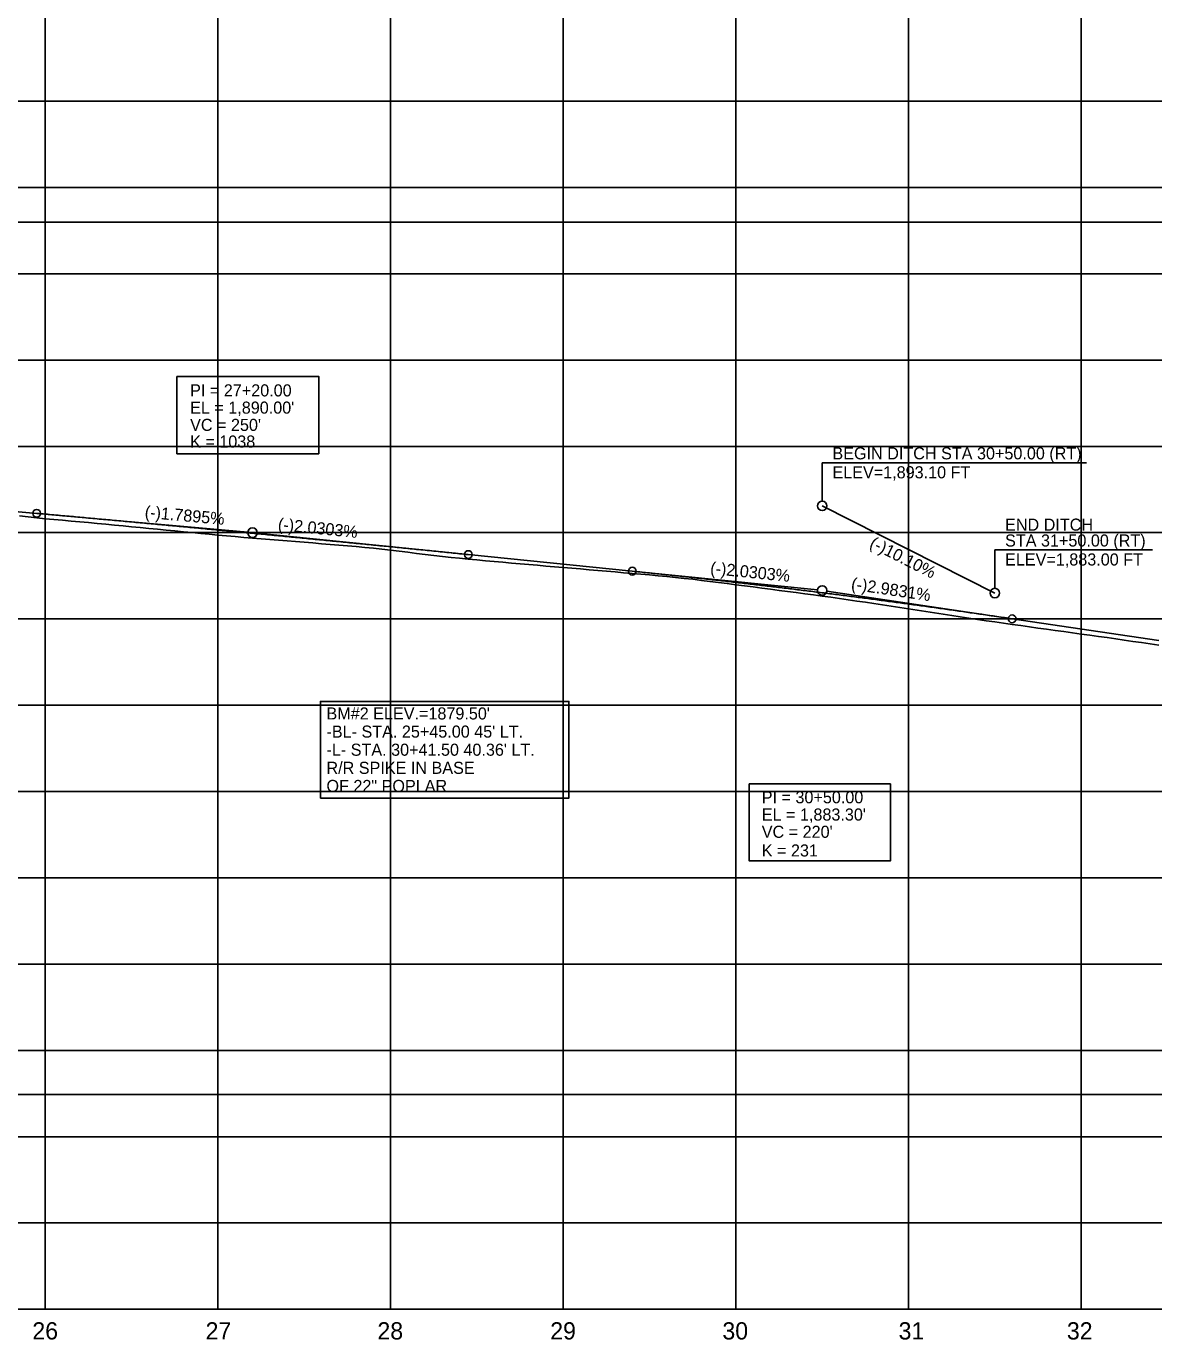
# Model space of a CAD drawing. Extents: x 553912 to 567693, y 512355 to 537539.
# Drawn here: x 558838 to 559491, y 513588 to 514349 of the extents above; entities that cross this region are included whole.
import ezdxf

# ---------------------------------------------------------------- set-up
doc = ezdxf.new("R2010")
doc.units = 0
for name, color, linetype in [('Exist DTM Spot Elevation Text', 7, 'Continuous'), ('Exist Profile Cell', 7, 'Continuous'), ('Exist Vertical Profile Ground Line', 7, 'Continuous'), ('Exist Vertical Profile Horizontal Axis Label Major', 7, 'Continuous'), ('Prop Vertical Profile Curve Label', 7, 'Continuous'), ('Prop Vertical Profile Ditch Grade Right', 7, 'Continuous'), ('Prop Vertical Profile Ditch Grade Right Label', 7, 'Continuous'), ('Prop Vertical Profile Grade', 7, 'Continuous'), ('Prop Vertical Profile Grade Label', 7, 'Continuous'), ('Prop VPI Label', 7, 'Continuous'), ('Scratch_Level_5', 7, 'Continuous'), ('Sheet Profile Grid Major CELL', 7, 'Continuous')]:
    doc.layers.add(name, color=color, linetype=linetype)

msp = doc.modelspace()

# ---------------------------------------------------------------- linework, layer by layer
at = {"layer": 'Exist DTM Spot Elevation Text'}
msp.add_lwpolyline([(559008.8, 513901.64), (559152.74, 513901.64), (559152.74, 513957.64), (559008.8, 513957.64)], close=True, dxfattribs=at)
at = {"layer": 'Exist Profile Cell'}
msp.add_line((557249.45, 513605.4), (563849.45, 513605.4), dxfattribs=at)
msp.add_line((557249.45, 513605.4), (563849.45, 513605.4), dxfattribs=at)
at = {"layer": 'Exist Vertical Profile Ground Line'}
for points in [[(558834.45, 514065.1), (558839.45, 514064.48), (558844.45, 514063.94), (558849.45, 514063.49), (558854.45, 514063.04), (558859.45, 514062.59), (558864.45, 514062.14), (558869.45, 514061.69), (558874.45, 514061.24), (558879.45, 514060.79), (558884.45, 514060.32), (558889.45, 514059.83), (558894.45, 514059.35), (558899.45, 514058.86), (558904.45, 514058.37), (558909.45, 514057.89), (558914.45, 514057.41), (558919.45, 514056.93), (558924.45, 514056.45), (558929.45, 514055.97), (558934.45, 514055.48), (558939.45, 514055), (558944.45, 514054.52), (558949.45, 514054.04), (558954.45, 514053.57), (558959.45, 514053.09), (558964.45, 514052.69), (558969.45, 514052.29), (558974.45, 514051.88), (558979.45, 514051.47), (558984.45, 514051.06), (558989.45, 514050.65), (558994.45, 514050.24), (558999.45, 514049.83), (559004.45, 514049.43), (559009.45, 514049), (559014.45, 514048.58), (559019.45, 514048.15), (559024.45, 514047.73), (559029.45, 514047.3), (559034.45, 514046.83), (559039.45, 514046.4), (559044.45, 514045.87), (559049.45, 514045.25), (559054.45, 514044.64), (559059.45, 514044.02), (559064.45, 514043.4), (559069.45, 514042.79), (559074.45, 514042.19), (559079.45, 514041.57), (559084.45, 514041.05), (559089.45, 514040.58), (559094.45, 514040.1), (559099.45, 514039.63), (559104.45, 514039.15), (559109.45, 514038.68), (559114.45, 514038.22), (559119.45, 514037.74), (559124.45, 514037.32), (559129.45, 514036.91), (559134.45, 514036.49), (559139.45, 514036.08), (559144.45, 514035.66), (559149.45, 514035.23), (559154.45, 514034.79), (559159.45, 514034.36), (559164.45, 514033.93), (559169.45, 514033.5), (559174.45, 514033.08), (559179.45, 514032.64), (559184.45, 514032.21), (559189.45, 514031.78), (559194.45, 514031.34), (559199.45, 514030.9), (559204.45, 514030.46), (559209.45, 514029.98), (559214.45, 514029.46), (559219.45, 514028.93), (559224.45, 514028.38), (559229.45, 514027.77), (559234.45, 514027.14), (559239.45, 514026.51), (559244.45, 514025.87), (559249.45, 514025.22)], [(558834.45, 514065.1), (558839.45, 514064.48), (558844.45, 514063.94), (558849.45, 514063.49), (558854.45, 514063.04), (558859.45, 514062.59), (558864.45, 514062.14), (558869.45, 514061.69), (558874.45, 514061.24), (558879.45, 514060.79), (558884.45, 514060.32), (558889.45, 514059.83), (558894.45, 514059.35), (558899.45, 514058.86), (558904.45, 514058.37), (558909.45, 514057.89), (558914.45, 514057.41), (558919.45, 514056.93), (558924.45, 514056.45), (558929.45, 514055.97), (558934.45, 514055.48), (558939.45, 514055), (558944.45, 514054.52), (558949.45, 514054.04), (558954.45, 514053.57), (558959.45, 514053.09), (558964.45, 514052.69), (558969.45, 514052.29), (558974.45, 514051.88), (558979.45, 514051.47), (558984.45, 514051.06), (558989.45, 514050.65), (558994.45, 514050.24), (558999.45, 514049.83), (559004.45, 514049.43), (559009.45, 514049), (559014.45, 514048.58), (559019.45, 514048.15), (559024.45, 514047.73), (559029.45, 514047.3), (559034.45, 514046.83), (559039.45, 514046.4), (559044.45, 514045.87), (559049.45, 514045.25), (559054.45, 514044.64), (559059.45, 514044.02), (559064.45, 514043.4), (559069.45, 514042.79), (559074.45, 514042.19), (559079.45, 514041.57), (559084.45, 514041.05), (559089.45, 514040.58), (559094.45, 514040.1), (559099.45, 514039.63), (559104.45, 514039.15), (559109.45, 514038.68), (559114.45, 514038.22), (559119.45, 514037.74), (559124.45, 514037.32), (559129.45, 514036.91), (559134.45, 514036.49), (559139.45, 514036.08), (559144.45, 514035.66), (559149.45, 514035.23), (559154.45, 514034.79), (559159.45, 514034.36), (559164.45, 514033.93), (559169.45, 514033.5), (559174.45, 514033.08), (559179.45, 514032.64), (559184.45, 514032.21), (559189.45, 514031.78), (559194.45, 514031.34), (559199.45, 514030.9), (559204.45, 514030.46), (559209.45, 514029.98), (559214.45, 514029.46), (559219.45, 514028.93), (559224.45, 514028.38), (559229.45, 514027.77), (559234.45, 514027.14), (559239.45, 514026.51), (559244.45, 514025.87), (559249.45, 514025.22)], [(559249.45, 514025.22), (559254.45, 514024.57), (559259.45, 514023.92), (559264.45, 514023.27), (559269.45, 514022.62), (559274.45, 514021.97), (559279.45, 514021.32), (559284.45, 514020.66), (559289.45, 514019.99), (559294.45, 514019.33), (559299.45, 514018.64), (559304.45, 514017.93), (559309.45, 514017.23), (559314.45, 514016.52), (559319.45, 514015.77), (559324.45, 514015.03), (559329.45, 514014.28), (559334.45, 514013.53), (559339.45, 514012.76), (559344.45, 514011.98), (559349.45, 514011.21), (559354.45, 514010.45), (559359.45, 514009.67), (559364.45, 514008.9), (559369.45, 514008.13), (559374.45, 514007.37), (559379.45, 514006.62), (559384.45, 514005.87), (559389.45, 514005.12), (559394.45, 514004.39), (559399.45, 514003.67), (559404.45, 514002.94), (559409.45, 514002.23), (559414.45, 514001.52), (559419.45, 514000.81), (559424.45, 514000.1), (559429.45, 513999.39), (559434.45, 513998.69), (559439.45, 513998.06), (559444.45, 513997.36), (559449.45, 513996.66), (559454.45, 513996), (559459.45, 513995.32), (559464.45, 513994.62), (559469.45, 513993.92), (559474.45, 513993.11), (559479.45, 513992.39), (559484.45, 513991.68), (559489.45, 513990.95), (559494.45, 513990.2)], [(559249.45, 514025.22), (559254.45, 514024.57), (559259.45, 514023.92), (559264.45, 514023.27), (559269.45, 514022.62), (559274.45, 514021.97), (559279.45, 514021.32), (559284.45, 514020.66), (559289.45, 514019.99), (559294.45, 514019.33), (559299.45, 514018.64), (559304.45, 514017.93), (559309.45, 514017.23), (559314.45, 514016.52), (559319.45, 514015.77), (559324.45, 514015.03), (559329.45, 514014.28), (559334.45, 514013.53), (559339.45, 514012.76), (559344.45, 514011.98), (559349.45, 514011.21), (559354.45, 514010.45), (559359.45, 514009.67), (559364.45, 514008.9), (559369.45, 514008.13), (559374.45, 514007.37), (559379.45, 514006.62), (559384.45, 514005.87), (559389.45, 514005.12), (559394.45, 514004.39), (559399.45, 514003.67), (559404.45, 514002.94), (559409.45, 514002.23), (559414.45, 514001.52), (559419.45, 514000.81), (559424.45, 514000.1), (559429.45, 513999.39), (559434.45, 513998.69), (559439.45, 513998.06), (559444.45, 513997.36), (559449.45, 513996.66), (559454.45, 513996), (559459.45, 513995.32), (559464.45, 513994.62), (559469.45, 513993.92), (559474.45, 513993.11), (559479.45, 513992.39), (559484.45, 513991.68), (559489.45, 513990.95), (559494.45, 513990.2)]]:
    msp.add_lwpolyline(points, dxfattribs=at)
at = {"layer": 'Prop Vertical Profile Curve Label'}
for centre in [(558844.45, 514066.58), (559094.45, 514042.71), (559189.45, 514033.07), (559409.45, 514005.49)]:
    msp.add_circle(centre, 2.25, dxfattribs=at)
at = {"layer": 'Prop Vertical Profile Ditch Grade Right'}
msp.add_line((559299.45, 514070.9), (559399.45, 514020.4), dxfattribs=at)
at = {"layer": 'Prop Vertical Profile Ditch Grade Right Label'}
for p, q in [((559299.45, 514073.65), (559299.45, 514095.87)), ((559452.63, 514095.87), (559299.45, 514095.87)), ((559399.45, 514023.15), (559399.45, 514045.37)), ((559490.78, 514045.37), (559399.45, 514045.37))]:
    msp.add_line(p, q, dxfattribs=at)
for centre in [(559299.45, 514070.9), (559399.45, 514020.4)]:
    msp.add_circle(centre, 2.75, dxfattribs=at)
at = {"layer": 'Prop Vertical Profile Grade'}
for p, q in [((558506.95, 514096.78), (558844.45, 514066.58)), ((559094.45, 514042.71), (559189.45, 514033.07)), ((559409.45, 514005.49), (559494.45, 513992.82))]:
    msp.add_line(p, q, dxfattribs=at)
for points in [[(558844.45, 514066.58), (558849.45, 514066.14), (558854.45, 514065.69), (558859.45, 514065.24), (558864.45, 514064.79), (558869.45, 514064.33), (558874.45, 514063.88), (558879.45, 514063.42), (558884.45, 514062.97), (558889.45, 514062.51), (558894.45, 514062.05), (558899.45, 514061.59), (558904.45, 514061.13), (558909.45, 514060.67), (558914.45, 514060.2), (558919.45, 514059.74), (558924.45, 514059.27), (558929.45, 514058.81), (558934.45, 514058.34), (558939.45, 514057.87), (558944.45, 514057.4), (558949.45, 514056.92), (558954.45, 514056.45), (558959.45, 514055.98), (558964.45, 514055.5), (558969.45, 514055.02), (558974.45, 514054.55), (558979.45, 514054.07), (558984.45, 514053.59), (558989.45, 514053.1), (558994.45, 514052.62), (558999.45, 514052.14), (559004.45, 514051.65), (559009.45, 514051.17), (559014.45, 514050.68), (559019.45, 514050.19), (559024.45, 514049.7), (559029.45, 514049.21), (559034.45, 514048.72), (559039.45, 514048.22), (559044.45, 514047.73), (559049.45, 514047.23), (559054.45, 514046.73), (559059.45, 514046.23), (559064.45, 514045.73), (559069.45, 514045.23), (559074.45, 514044.73), (559079.45, 514044.23), (559084.45, 514043.72), (559089.45, 514043.22), (559094.45, 514042.71)], [(559189.45, 514033.07), (559193.85, 514032.62), (559198.25, 514032.17), (559202.65, 514031.71), (559207.05, 514031.25), (559211.45, 514030.78), (559215.85, 514030.31), (559220.25, 514029.84), (559224.65, 514029.36), (559229.05, 514028.88), (559233.45, 514028.39), (559237.85, 514027.9), (559242.25, 514027.41), (559246.65, 514026.91), (559251.05, 514026.4), (559255.45, 514025.9), (559259.85, 514025.38), (559264.25, 514024.87), (559268.65, 514024.35), (559273.05, 514023.82), (559277.45, 514023.3), (559281.85, 514022.76), (559286.25, 514022.23), (559290.65, 514021.68), (559295.05, 514021.14), (559299.45, 514020.59), (559303.85, 514020.04), (559308.25, 514019.48), (559312.65, 514018.92), (559317.05, 514018.35), (559321.45, 514017.78), (559325.85, 514017.21), (559330.25, 514016.63), (559334.65, 514016.04), (559339.05, 514015.46), (559343.45, 514014.87), (559347.85, 514014.27), (559352.25, 514013.67), (559356.65, 514013.07), (559361.05, 514012.46), (559365.45, 514011.85), (559369.85, 514011.23), (559374.25, 514010.61), (559378.65, 514009.98), (559383.05, 514009.36), (559387.45, 514008.72), (559391.85, 514008.09), (559396.25, 514007.44), (559400.65, 514006.8), (559405.05, 514006.15), (559409.45, 514005.49)]]:
    msp.add_spline(points, degree=3, dxfattribs=at)
at = {"layer": 'Prop VPI Label'}
for p, q in [((558844.45, 514066.58), (558966.71, 514055.65)), ((559094.45, 514042.71), (558972.19, 514055.12)), ((559189.45, 514033.07), (559296.72, 514022.18)), ((559409.45, 514005.49), (559302.17, 514021.49))]:
    msp.add_line(p, q, dxfattribs=at)
for points in [[(558925.69, 514145.97), (559007.81, 514145.97), (559007.81, 514101.15), (558925.69, 514101.15)], [(559257.22, 513909.83), (559338.96, 513909.83), (559338.96, 513865.22), (559257.22, 513865.22)]]:
    msp.add_lwpolyline(points, close=True, dxfattribs=at)
for centre in [(558969.45, 514055.4), (559299.45, 514021.9)]:
    msp.add_circle(centre, 2.75, dxfattribs=at)
at = {"layer": 'Scratch_Level_5'}
msp.add_lwpolyline([(558649.45, 514235.4), (558643.76, 513729.91), (560043.76, 513729.91), (560049.45, 514074.35), (559899.4, 514074.35), (559899.4, 514235.4)], close=True, dxfattribs=at)
at = {"layer": 'Sheet Profile Grid Major CELL'}
for p, q in [((558849.45, 513605.4), (558849.45, 514805.4)), ((558949.45, 513605.4), (558949.45, 514805.4)), ((559049.45, 513605.4), (559049.45, 514805.4)), ((559149.45, 513605.4), (559149.45, 514805.4)), ((559249.45, 513605.4), (559249.45, 514805.4)), ((559349.45, 513605.4), (559349.45, 514805.4)), ((559449.45, 513605.4), (559449.45, 514805.4)), ((563849.45, 514305.4), (557249.45, 514305.4)), ((563849.45, 514255.4), (557249.45, 514255.4)), ((563849.45, 514205.4), (557249.45, 514205.4)), ((563849.45, 514155.4), (557249.45, 514155.4)), ((563849.45, 514105.4), (557249.45, 514105.4)), ((563849.45, 514055.4), (557249.45, 514055.4)), ((563849.45, 514005.4), (557249.45, 514005.4)), ((563849.45, 513955.4), (557249.45, 513955.4)), ((563849.45, 513905.4), (557249.45, 513905.4)), ((563849.45, 513855.4), (557249.45, 513855.4)), ((563849.45, 513805.4), (557249.45, 513805.4)), ((563849.45, 513755.4), (557249.45, 513755.4)), ((563849.45, 513705.4), (557249.45, 513705.4)), ((563849.45, 513655.4), (557249.45, 513655.4))]:
    msp.add_line(p, q, dxfattribs=at)

# ---------------------------------------------------------------- texts
at = {"layer": 'Exist DTM Spot Elevation Text'}
for s, p in [("BM#2 ELEV.=1879.50'", (559012.3, 513947.14)), ("-BL- STA. 25+45.00 45' LT.", (559012.3, 513936.64)), ("-L- STA. 30+41.50 40.36' LT.", (559012.3, 513926.14)), ('R/R SPIKE IN BASE', (559012.3, 513915.64)), ('OF 22" POPLAR', (559012.3, 513905.14))]:
    msp.add_text(s, height=7, dxfattribs=at).set_placement(p)
at = {"layer": 'Exist Vertical Profile Horizontal Axis Label Major'}
for s, p in [('26', (558841.94, 513587.9)), ('26', (558841.94, 513587.9)), ('27', (558942.3, 513587.9)), ('27', (558942.3, 513587.9)), ('28', (559041.83, 513587.9)), ('28', (559041.83, 513587.9)), ('29', (559141.92, 513587.9)), ('29', (559141.92, 513587.9)), ('30', (559241.64, 513587.9)), ('30', (559241.64, 513587.9)), ('31', (559343.71, 513587.9)), ('31', (559343.71, 513587.9)), ('32', (559441.21, 513587.9)), ('32', (559441.21, 513587.9))]:
    msp.add_text(s, height=10, dxfattribs=at).set_placement(p)
at = {"layer": 'Prop Vertical Profile Curve Label'}
for s, p in [("VC = 250'", (558933.32, 514114.35)), ('K = 1038', (558933.32, 514104.7)), ("VC = 220'", (559264.45, 513878.58)), ('K = 231', (559264.45, 513867.76))]:
    msp.add_text(s, height=7, dxfattribs=at).set_placement(p)
at = {"layer": 'Prop Vertical Profile Ditch Grade Right'}
for s, p in [('BEGIN DITCH STA 30+50.00 (RT)', (559305.38, 514097.87)), ('END DITCH', (559405.38, 514056.54)), ('STA 31+50.00 (RT)', (559405.38, 514047.37))]:
    msp.add_text(s, height=7, dxfattribs=at).set_placement(p)
at = {"layer": 'Prop Vertical Profile Ditch Grade Right Label'}
for s, p in [('ELEV=1,893.10 FT', (559305.38, 514086.87)), ('ELEV=1,883.00 FT', (559405.38, 514036.37))]:
    msp.add_text(s, height=7, dxfattribs=at).set_placement(p)
msp.add_text('(-)10.10%', height=7, rotation=333.20622, dxfattribs=at).set_placement((559326.35, 514047.13))
at = {"layer": 'Prop Vertical Profile Grade Label'}
for s, rotation, p in [('(-)1.7895%', 354.88715, (558906.83, 514064.02)), ('(-)2.0303%', 354.20347, (558983.95, 514056.94)), ('(-)2.0303%', 354.20347, (559234.36, 514031.52)), ('(-)2.9831%', 351.51673, (559315.91, 514022.48))]:
    msp.add_text(s, height=7, rotation=rotation, dxfattribs=at).set_placement(p)
at = {"layer": 'Prop VPI Label'}
for s, p in [('PI = 27+20.00', (558933.32, 514134.35)), ("EL = 1,890.00'", (558933.32, 514124.35)), ('PI = 30+50.00', (559264.45, 513898.58)), ("EL = 1,883.30'", (559264.45, 513888.58))]:
    msp.add_text(s, height=7, dxfattribs=at).set_placement(p)

doc.saveas('drawing.dxf')
